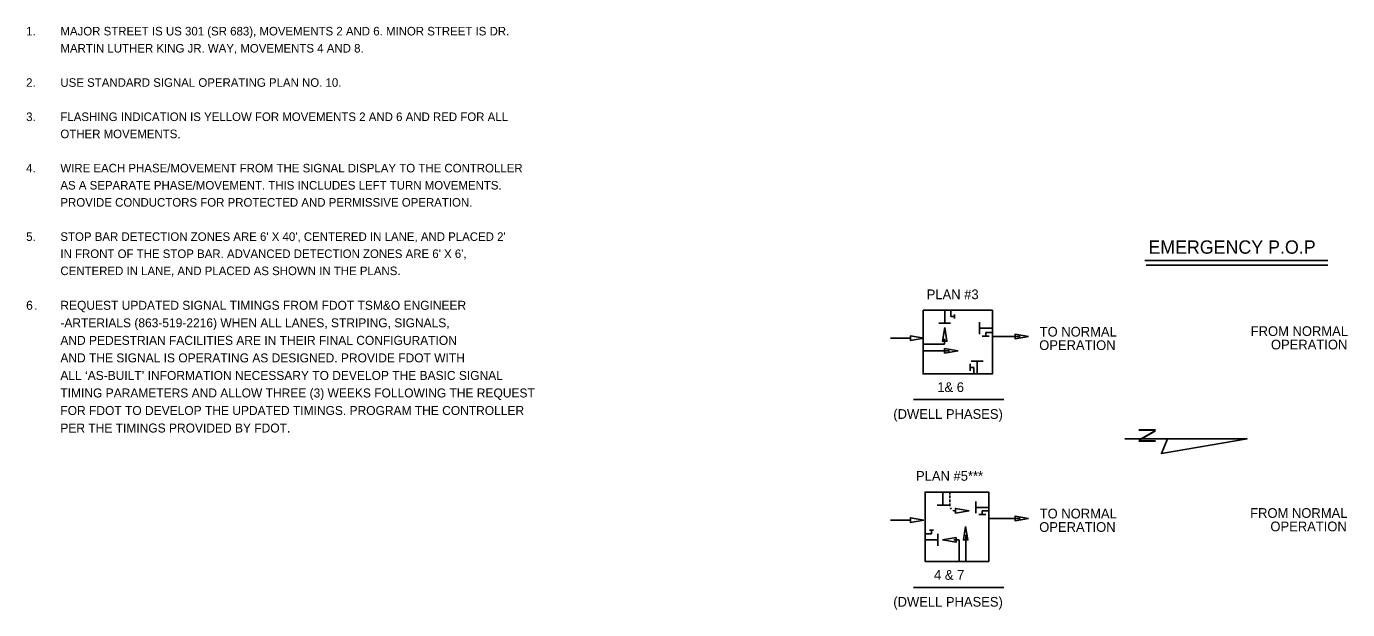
# Model space of a CAD drawing. Extents: x 0 to 1428, y -128 to 567.
# Drawn here: x -0.115 to 0.712, y 0.965 to 1.33 of the extents above; entities that cross this region are included whole.
import ezdxf

# ---------------------------------------------------------------- set-up
doc = ezdxf.new("R2010")
doc.units = 0
for name, color, linetype in [('Default', 7, 'Continuous'), ('NorthArw_dp', 7, 'Continuous'), ('TextLabel', 7, 'Continuous')]:
    doc.layers.add(name, color=color, linetype=linetype)

msp = doc.modelspace()

# ---------------------------------------------------------------- linework, layer by layer
at = {"layer": 'NorthArw_dp'}
msp.add_line((0.57277, 1.07221), (0.64939, 1.07221), dxfattribs=at)
msp.add_lwpolyline([(0.59959, 1.07221), (0.64939, 1.07221), (0.59576, 1.06302)], close=True, dxfattribs=at)
at = {"layer": 'TextLabel'}
for p, q in [((0.58542, 1.18374), (0.69995, 1.18374)), ((0.58626, 1.18097), (0.69995, 1.18097)), ((0.46012, 1.14798), (0.46012, 1.15273)), ((0.46012, 1.15268), (0.46012, 1.14464)), ((0.46388, 1.15274), (0.46388, 1.14869)), ((0.46626, 1.14869), (0.46626, 1.15)), ((0.46626, 1.15), (0.46626, 1.1475)), ((0.46381, 1.14464), (0.45643, 1.14464)), ((0.46388, 1.14869), (0.46626, 1.14869)), ((0.4819, 1.13782), (0.4819, 1.1452)), ((0.48994, 1.14151), (0.4819, 1.14151)), ((0.43864, 1.13523), (0.4262, 1.13523)), ((0.46005, 1.1315), (0.46005, 1.13482)), ((0.48795, 1.13643), (0.4836, 1.13643)), ((0.48982, 1.13881), (0.48577, 1.13881)), ((0.48577, 1.13881), (0.48577, 1.13643)), ((0.50733, 1.13622), (0.49066, 1.13622)), ((0.46005, 1.13144), (0.44651, 1.13144)), ((0.46318, 1.12727), (0.44651, 1.12727)), ((0.47597, 1.11478), (0.47597, 1.11914)), ((0.47835, 1.11696), (0.47597, 1.11696)), ((0.47673, 1.12086), (0.48411, 1.12086)), ((0.47835, 1.11291), (0.47835, 1.11696)), ((0.48042, 1.11281), (0.48042, 1.12086)), ((0.44055, 1.09678), (0.49707, 1.09678)), ((0.45905, 1.03887), (0.45905, 1.03083)), ((0.46342, 1.03895), (0.46342, 1.03753)), ((0.46343, 1.03673), (0.46343, 1.03508)), ((0.46343, 1.03424), (0.46343, 1.03259)), ((0.46274, 1.03083), (0.45537, 1.03083)), ((0.46343, 1.03178), (0.46343, 1.03014)), ((0.47971, 1.02567), (0.47971, 1.03304)), ((0.48775, 1.02936), (0.47971, 1.02936)), ((0.48765, 1.02728), (0.4836, 1.02728)), ((0.4836, 1.02728), (0.4836, 1.0249)), ((0.43864, 1.02145), (0.4262, 1.02145)), ((0.48578, 1.0249), (0.48143, 1.0249)), ((0.50733, 1.02245), (0.48767, 1.02245)), ((0.44783, 1.01282), (0.45188, 1.01282)), ((0.45258, 1.00905), (0.44784, 1.00905)), ((0.44789, 1.00905), (0.45593, 1.00905)), ((0.45188, 1.0152), (0.45057, 1.0152)), ((0.45057, 1.0152), (0.45307, 1.0152)), ((0.45188, 1.01282), (0.45188, 1.0152)), ((0.45593, 1.01274), (0.45593, 1.00537)), ((0.46907, 1.00899), (0.46574, 1.00899)), ((0.46913, 1.00899), (0.46913, 0.99544)), ((0.47329, 1.01211), (0.47329, 0.99544)), ((0.44055, 0.97931), (0.49707, 0.97931))]:
    msp.add_line(p, q, dxfattribs=at)
for points in [[(0.4466, 1.15273), (0.49002, 1.15273), (0.49002, 1.1129), (0.4466, 1.1129)], [(0.46012, 1.14182), (0.45868, 1.13335), (0.46155, 1.13335)], [(0.4471, 1.13523), (0.43864, 1.13666), (0.43864, 1.13379)], [(0.51267, 1.13628), (0.5042, 1.13772), (0.5042, 1.13485)], [(0.46852, 1.12733), (0.46005, 1.12876), (0.46005, 1.1259)], [(0.44784, 0.99554), (0.44784, 1.03895), (0.48767, 1.03895), (0.48767, 0.99554)], [(0.47535, 1.02725), (0.46688, 1.02869), (0.46688, 1.02582)], [(0.4471, 1.02145), (0.43864, 1.02288), (0.43864, 1.02002)], [(0.47323, 1.01745), (0.4718, 1.00899), (0.47467, 1.00899)], [(0.51267, 1.02251), (0.5042, 1.02394), (0.5042, 1.02107)], [(0.45875, 1.00905), (0.46721, 1.00762), (0.46721, 1.01049)]]:
    msp.add_lwpolyline(points, close=True, dxfattribs=at)
for start, end in [(203.2123, 222.21241), (246.80153, 276.00238)]:
    msp.add_arc((0.46655, 1.03037), 0.00313, start, end, dxfattribs=at)

# ---------------------------------------------------------------- texts
at = {"layer": 'Default'}
for s, height, p in [('1.', 0.005355, (-0.11472, 1.32461)), ('MAJOR STREET IS US 301 (SR 683), MOVEMENTS 2 AND 6. MINOR STREET IS DR. ', 0.005355, (-0.09329, 1.32461)), ('MARTIN LUTHER KING JR. WAY, MOVEMENTS 4 AND 8.', 0.005355, (-0.09329, 1.3139)), ('2. ', 0.005355, (-0.11472, 1.29248)), ('USE STANDARD SIGNAL OPERATING PLAN NO. 10.', 0.005355, (-0.09329, 1.29248)), ('3. ', 0.005355, (-0.11472, 1.27106)), ('FLASHING INDICATION IS YELLOW FOR MOVEMENTS 2 AND 6 AND RED FOR ALL ', 0.005355, (-0.09329, 1.27106)), ('OTHER MOVEMENTS.', 0.005355, (-0.09329, 1.26035)), ('4. ', 0.005355, (-0.11472, 1.23893)), ('WIRE EACH PHASE/MOVEMENT FROM THE SIGNAL DISPLAY TO THE CONTROLLER ', 0.005355, (-0.09329, 1.23893)), ('AS A SEPARATE PHASE/MOVEMENT. THIS INCLUDES LEFT TURN MOVEMENTS. ', 0.005355, (-0.09329, 1.22822)), ('PROVIDE CONDUCTORS FOR PROTECTED AND PERMISSIVE OPERATION.', 0.005355, (-0.09329, 1.21751)), ('5. ', 0.005355, (-0.11472, 1.19609)), ("STOP BAR DETECTION ZONES ARE 6' X 40', CENTERED IN LANE, AND PLACED 2' ", 0.005355, (-0.09329, 1.19609)), ("IN FRONT OF THE STOP BAR. ADVANCED DETECTION ZONES ARE 6' X 6', ", 0.005355, (-0.09329, 1.18538)), ('CENTERED IN LANE, AND PLACED AS SHOWN IN THE PLANS.', 0.005355, (-0.09329, 1.17467)), ('6', 0.00561, (-0.11472, 1.15299)), ('REQUEST UPDATED SIGNAL TIMINGS FROM FDOT TSM&O ENGINEER ', 0.0056123, (-0.09329, 1.15299)), ('. ', 0.005355, (-0.10968, 1.15299)), ('-ARTERIALS (863-519-2216) WHEN ALL LANES, STRIPING, SIGNALS, ', 0.0056123, (-0.09329, 1.14202)), ('AND PEDESTRIAN FACILITIES ARE IN THEIR FINAL CONFIGURATION ', 0.0056123, (-0.09329, 1.13105)), ('AND THE SIGNAL IS OPERATING AS DESIGNED. PROVIDE FDOT WITH ', 0.0056123, (-0.09329, 1.12009)), ('ALL ‘AS-BUILT’ INFORMATION NECESSARY TO DEVELOP THE BASIC SIGNAL ', 0.0056123, (-0.09329, 1.10912)), ('TIMING PARAMETERS AND ALLOW THREE (3) WEEKS FOLLOWING THE REQUEST', 0.0056123, (-0.09329, 1.09815)), ('FOR FDOT TO DEVELOP THE UPDATED TIMINGS. PROGRAM THE CONTROLLER ', 0.0056123, (-0.09329, 1.08718)), ('PER THE TIMINGS PROVIDED BY FDOT.', 0.0056123, (-0.09329, 1.07622))]:
    msp.add_text(s, height=height, dxfattribs=at).set_placement(p)
at = {"layer": 'NorthArw_dp'}
msp.add_text('N', height=0.01072, rotation=270, dxfattribs=at).set_placement((0.58145, 1.07949))
at = {"layer": 'TextLabel'}
for s, height, p in [('EMERGENCY P.O.P', 0.0083333, (0.5876, 1.18807)), ('PLAN #3', 0.00607, (0.44886, 1.15963)), ('TO NORMAL', 0.00607, (0.51957, 1.13624)), ('FROM NORMAL', 0.0060697, (0.65165, 1.13661)), ('OPERATION', 0.00607, (0.51927, 1.12784)), ('OPERATION', 0.00607, (0.66431, 1.1282)), ('1& 6', 0.00607, (0.45549, 1.10156)), ('(DWELL PHASES)', 0.0060697, (0.42796, 1.08476)), ('PLAN #5***', 0.00607, (0.44218, 1.04604)), ('TO NORMAL', 0.00607, (0.51957, 1.02247)), ('FROM NORMAL', 0.0060697, (0.6513, 1.02283)), ('OPERATION', 0.00607, (0.51927, 1.01407)), ('OPERATION', 0.00607, (0.66396, 1.01443)), ('4 & 7', 0.00607, (0.45344, 0.98409)), ('(DWELL PHASES)', 0.0060697, (0.42796, 0.96729))]:
    msp.add_text(s, height=height, dxfattribs=at).set_placement(p)

doc.saveas('drawing.dxf')
